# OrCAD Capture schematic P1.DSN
size A
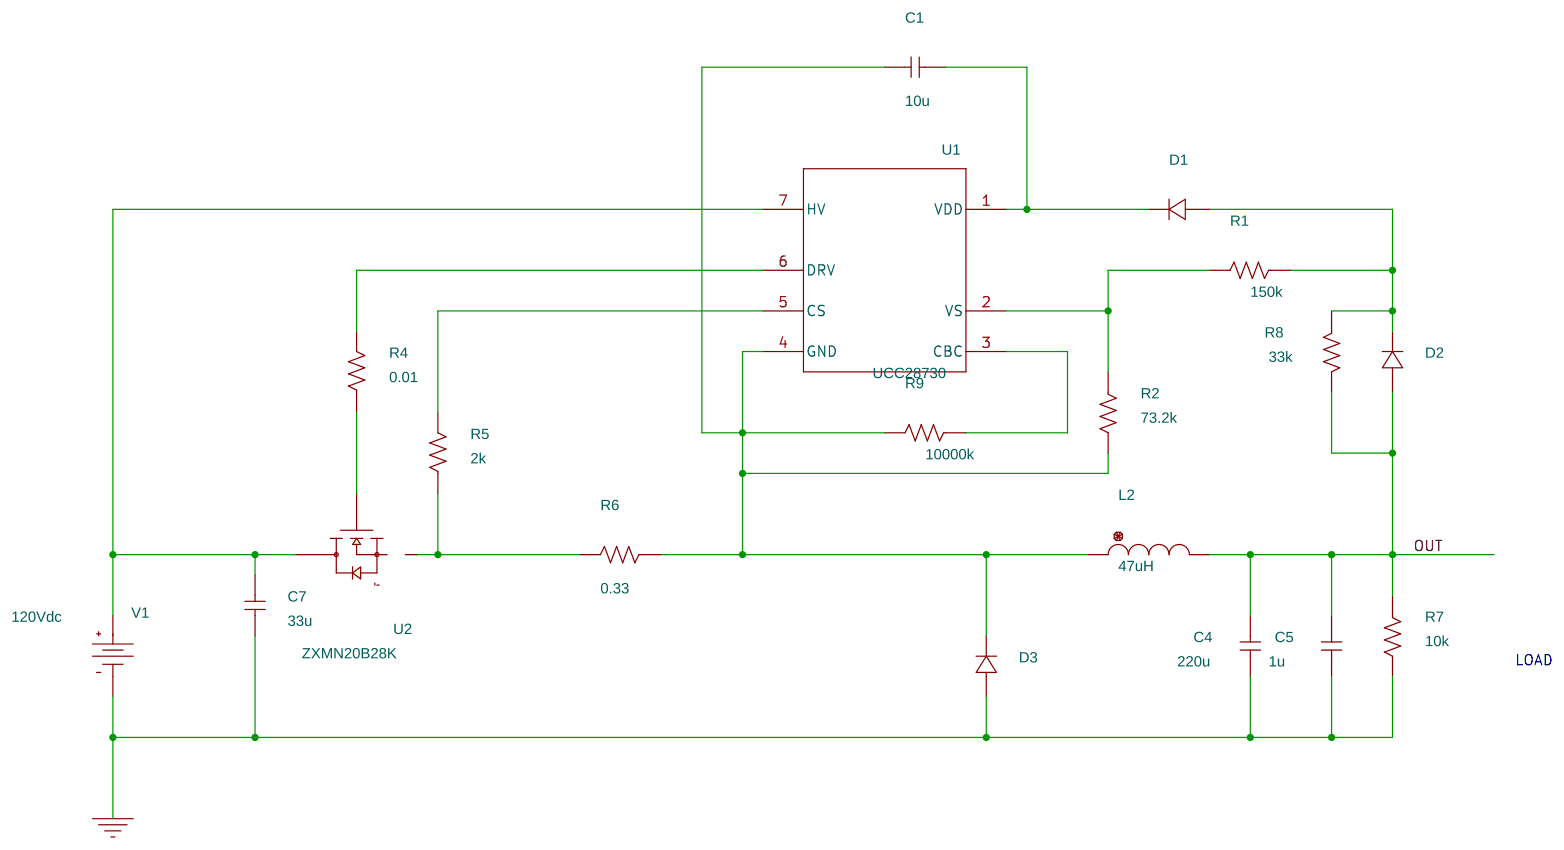
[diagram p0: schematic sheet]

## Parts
C1  10u  [cap196]
C4  220u  [cap196]
C5  1u  [cap196]
C7  33u  [cap196]
D1  Dbreak
D2  Dbreak
D3  Dbreak
L2  47uH  [DISC350x175LS200x100034]
R1  150k  [AXRC05]
R2  73.2k  [AXRC05]
R4  0.01  [AXRC05]
R5  2k  [AXRC05]
R6  0.33  [AXRC05]
R7  10k  [AXRC05]
R8  33k  [AXRC05]
R9  10000k  [AXRC05]
U1  UCC28730
U2  ZXMN20B28K
V1  VDC

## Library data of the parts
C1 C4 C5 C7 = C
D1-D3 = Dbreak
L2 = L
R1 R2 R4-R9 = R
U1 = UCC28730_NETLIST: Testbenches: []; Version: 1; productURL: http://www.ti.com/document-viewer/UCC24650/datasheet/
U2 = ZXMN20B28K
V1 = VDC: DC: 120Vdc

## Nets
0: C4.1 C5.1 C7.1 D3.0(1) R7.2 V1.1(-)
OUT: C4.2 C5.2 D2.0(1) L2.2 R7.1 R8.2
N00675: C7.2 U1.7(HV) U2.3(drain) V1.0(+)
N00701: R4.2 U1.6(DRV)
N00719: R5.1 R6.2 U2.1(source)
N00801: R5.2 U1.5(CS)
N00887: C1.2 D3.1(2) L2.1 R2.2 R6.1 R9.2 U1.4(GND)
N01106: D1.0(1) D2.1(2) R1.1 R8.1
N01228: R1.2 R2.1 U1.2(VS)
N01301: C1.1 D1.1(2) U1.1(VDD)
N02199: R4.1 U2.2(gate)
N16774780: R9.1 U1.3(CBC)

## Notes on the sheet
- LOAD
